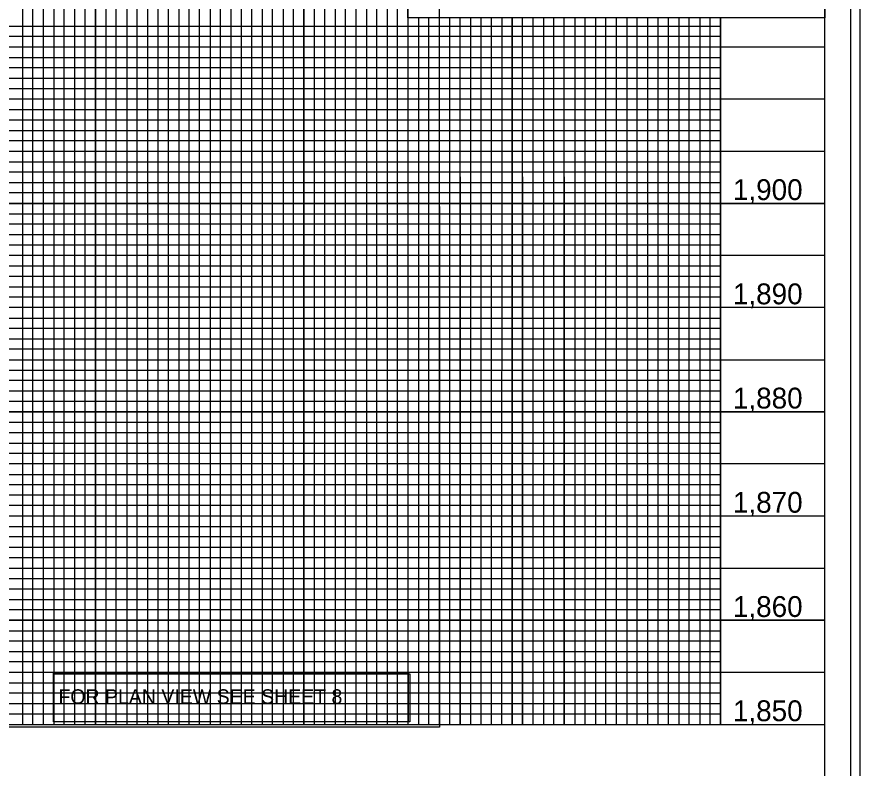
# Model space of a CAD drawing. Extents: x 557032 to 558716, y 525869 to 526969.
# Drawn here: x 558311.7 to 558716.5, y 526423.3 to 526783.7 of the extents above; entities that cross this region are included whole.
import ezdxf

# ---------------------------------------------------------------- set-up
doc = ezdxf.new("R2010")
doc.units = 0
for name, color, linetype in [('Exist Vertical Profile Vertical Axis Label', 7, 'Continuous'), ('Prop VPI Label', 7, 'Continuous'), ('Scratch_Level_5', 7, 'Continuous'), ('Sheet DOT Grid CELL', 7, 'Continuous'), ('Sheet Layout Profile Border Port 1', 7, 'Continuous'), ('Sheet Plot Border Inside CELL', 7, 'Continuous'), ('Sheet Plot Border Outside CELL', 7, 'Continuous'), ('Sheet Profile CELL', 7, 'Continuous'), ('Sheet Profile Grid Major CELL', 7, 'Continuous'), ('Sheet Profile Grid Middle CELL', 7, 'Continuous'), ('Sheet Profile Grid Minor CELL', 7, 'Continuous'), ('Sheet Sticker Exception Certification CELL', 7, 'Continuous')]:
    doc.layers.add(name, color=color, linetype=linetype)

msp = doc.modelspace()

# ---------------------------------------------------------------- linework, layer by layer
at = {"layer": 'Prop VPI Label'}
for points in [[(558329.22, 526469.22), (558499.45, 526469.22), (558499.45, 526445.55), (558329.22, 526445.55)], [(558329.22, 526468.46), (558500.36, 526468.46), (558500.36, 526445.55), (558329.22, 526445.55)]]:
    msp.add_lwpolyline(points, close=True, dxfattribs=at)
at = {"layer": 'Scratch_Level_5'}
msp.add_lwpolyline([(557999.45, 526942.96), (558514.45, 526942.96), (558514.5, 526442.96), (557999.5, 526442.96)], close=True, dxfattribs=at)
at = {"layer": 'Sheet DOT Grid CELL'}
for p, q in [((558349.45, 526444.22), (558349.45, 526944.22)), ((558399.45, 526444.22), (558399.45, 526944.22)), ((558449.45, 526444.22), (558449.45, 526944.22)), ((558499.45, 526444.22), (558499.45, 526806.67)), ((558549.45, 526444.22), (558549.45, 526783.17)), ((558599.45, 526444.22), (558599.45, 526783.17)), ((558649.45, 526444.22), (558649.45, 526783.17)), ((558699.45, 526694.22), (557199.45, 526694.22)), ((558699.45, 526644.22), (557199.45, 526644.22)), ((558699.45, 526594.22), (557199.45, 526594.22)), ((558699.45, 526544.22), (557199.45, 526544.22)), ((558699.45, 526494.22), (557199.45, 526494.22))]:
    msp.add_line(p, q, dxfattribs=at)
at = {"layer": 'Sheet Layout Profile Border Port 1'}
msp.add_lwpolyline([(557249.45, 526783.17), (557249.45, 526444.22), (558649.45, 526444.22), (558649.45, 526783.17)], dxfattribs=at)
at = {"layer": 'Sheet Plot Border Inside CELL'}
msp.add_lwpolyline([(557045.45, 525891.67), (558711.95, 525891.67), (558711.95, 526946.77), (557045.45, 526946.77)], close=True, dxfattribs=at)
at = {"layer": 'Sheet Plot Border Outside CELL'}
msp.add_lwpolyline([(557032.45, 525869.22), (558716.45, 525869.22), (558716.45, 526969.22), (557032.45, 526969.22)], close=True, dxfattribs=at)
at = {"layer": 'Sheet Profile CELL'}
msp.add_line((557199.45, 526444.22), (558699.45, 526444.22), dxfattribs=at)
msp.add_lwpolyline([(558699.45, 526944.22), (557199.45, 526944.22), (557199.45, 525894.22), (558699.45, 525894.22)], close=True, dxfattribs=at)
at = {"layer": 'Sheet Profile Grid Major CELL'}
for points in [[(558299.45, 526944.22), (558349.45, 526944.22), (558349.45, 526444.22), (558399.45, 526444.22), (558399.45, 526944.22), (558449.45, 526944.22), (558449.45, 526444.22), (558499.45, 526444.22), (558499.45, 526944.22), (558525.75, 526944.22)], [(558649.45, 526783.17), (558649.45, 526444.22), (558699.45, 526444.22), (558699.45, 526794.22)], [(558549.45, 526783.17), (558549.45, 526444.22), (558599.45, 526444.22), (558599.45, 526444.22), (558599.45, 526783.17)], [(558699.45, 526744.22), (557199.45, 526744.22), (557199.45, 526694.22), (558699.45, 526694.22)], [(558699.45, 526644.22), (557199.45, 526644.22), (557199.45, 526594.22), (558699.45, 526594.22)], [(558699.45, 526544.22), (557199.45, 526544.22), (557199.45, 526544.22), (557199.45, 526494.22), (558699.45, 526494.22)]]:
    msp.add_lwpolyline(points, dxfattribs=at)
at = {"layer": 'Sheet Profile Grid Middle CELL'}
for points in [[(558274.45, 526444.22), (558324.45, 526444.22), (558324.45, 526944.22), (558374.45, 526944.22), (558374.45, 526444.22), (558424.45, 526444.22), (558424.45, 526944.22), (558474.45, 526944.22), (558474.45, 526444.22), (558524.45, 526444.22), (558524.45, 526783.17)], [(558524.45, 526707.02), (558524.45, 526444.22), (558574.45, 526444.22), (558574.45, 526783.17)], [(558574.45, 526707.02), (558574.45, 526444.22), (558624.45, 526444.22), (558624.45, 526783.17)], [(558699.45, 526769.22), (557199.45, 526769.22), (557199.45, 526719.22), (558524.45, 526719.22)], [(558524.45, 526719.22), (558699.45, 526719.22)], [(558699.45, 526669.22), (557199.45, 526669.22), (557199.45, 526619.22), (558699.45, 526619.22)], [(558699.45, 526569.22), (557199.45, 526569.22), (557199.45, 526519.22), (558699.45, 526519.22)], [(558699.45, 526469.22), (557199.45, 526469.22)]]:
    msp.add_lwpolyline(points, dxfattribs=at)
at = {"layer": 'Sheet Profile Grid Minor CELL'}
for p, q in [((557249.45, 526779.22), (558649.45, 526779.22)), ((558649.45, 526759.22), (557249.45, 526759.22)), ((557249.45, 526754.22), (558649.45, 526754.22)), ((558649.45, 526734.22), (557249.45, 526734.22)), ((557249.45, 526729.22), (558649.45, 526729.22)), ((558649.45, 526709.22), (557249.45, 526709.22)), ((557249.45, 526704.22), (558649.45, 526704.22)), ((558649.45, 526699.22), (557249.45, 526699.22)), ((557249.45, 526689.22), (558649.45, 526689.22)), ((558649.45, 526684.22), (557249.45, 526684.22)), ((557249.45, 526679.22), (558649.45, 526679.22)), ((558649.45, 526674.22), (557249.45, 526674.22)), ((557249.45, 526664.22), (558649.45, 526664.22)), ((558649.45, 526659.22), (557249.45, 526659.22)), ((557249.45, 526654.22), (558649.45, 526654.22)), ((558649.45, 526649.22), (557249.45, 526649.22)), ((557249.45, 526639.22), (558649.45, 526639.22)), ((558649.45, 526634.22), (557249.45, 526634.22)), ((557249.45, 526629.22), (558649.45, 526629.22)), ((558649.45, 526624.22), (557249.45, 526624.22)), ((557249.45, 526614.22), (558649.45, 526614.22)), ((558649.45, 526609.22), (557249.45, 526609.22)), ((557249.45, 526604.22), (558649.45, 526604.22)), ((558649.45, 526599.22), (557249.45, 526599.22)), ((557249.45, 526589.22), (558649.45, 526589.22)), ((558649.45, 526584.22), (557249.45, 526584.22)), ((557249.45, 526579.22), (558649.45, 526579.22)), ((558649.45, 526574.22), (557249.45, 526574.22)), ((557249.45, 526564.22), (558649.45, 526564.22)), ((558649.45, 526559.22), (557249.45, 526559.22)), ((558649.45, 526554.22), (557249.45, 526554.22)), ((558649.45, 526549.22), (557249.45, 526549.22)), ((557249.45, 526539.22), (558649.45, 526539.22)), ((558649.45, 526534.22), (557249.45, 526534.22)), ((557249.45, 526529.22), (558649.45, 526529.22)), ((558649.45, 526524.22), (557249.45, 526524.22)), ((557249.45, 526514.22), (558649.45, 526514.22)), ((558649.45, 526509.22), (557249.45, 526509.22)), ((557249.45, 526504.22), (558649.45, 526504.22)), ((558649.45, 526499.22), (557249.45, 526499.22)), ((557249.45, 526489.22), (558649.45, 526489.22)), ((558649.45, 526484.22), (557249.45, 526484.22)), ((557249.45, 526479.22), (558649.45, 526479.22)), ((558649.45, 526474.22), (557249.45, 526474.22)), ((557249.45, 526464.22), (558649.45, 526464.22)), ((558649.45, 526459.22), (557249.45, 526459.22)), ((557249.45, 526454.22), (558649.45, 526454.22))]:
    msp.add_line(p, q, dxfattribs=at)
for points in [[(558314.45, 526944.22), (558314.45, 526444.22), (558319.45, 526444.22), (558319.45, 526944.22)], [(558329.45, 526944.22), (558329.45, 526444.22), (558334.45, 526444.22), (558334.45, 526944.22)], [(558339.45, 526944.22), (558339.45, 526444.22), (558344.45, 526444.22), (558344.45, 526944.22)], [(558354.45, 526944.22), (558354.45, 526444.22), (558359.45, 526444.22), (558359.45, 526944.22)], [(558364.45, 526944.22), (558364.45, 526444.22), (558369.45, 526444.22), (558369.45, 526944.22)], [(558379.45, 526944.22), (558379.45, 526444.22), (558384.45, 526444.22), (558384.45, 526944.22)], [(558389.45, 526944.22), (558389.45, 526444.22)], [(558389.45, 526444.22), (558394.45, 526444.22), (558394.45, 526944.22)], [(558404.45, 526944.22), (558404.45, 526444.22), (558409.45, 526444.22), (558409.45, 526944.22)], [(558414.45, 526944.22), (558414.45, 526444.22), (558419.45, 526444.22), (558419.45, 526944.22)], [(558429.45, 526944.22), (558429.45, 526444.22), (558434.45, 526444.22), (558434.45, 526944.22)], [(558439.45, 526944.22), (558439.45, 526444.22), (558444.45, 526444.22), (558444.45, 526944.22)], [(558454.45, 526944.22), (558454.45, 526444.22), (558459.45, 526444.22), (558459.45, 526944.22)], [(558464.45, 526944.22), (558464.45, 526444.22), (558469.45, 526444.22), (558469.45, 526944.22)], [(558479.45, 526944.22), (558479.45, 526444.22), (558484.45, 526444.22), (558484.45, 526944.22)], [(558489.45, 526944.22), (558489.45, 526444.22), (558494.45, 526444.22), (558494.45, 526944.22)], [(558504.45, 526783.17), (558504.45, 526444.22), (558509.45, 526444.22), (558509.45, 526783.17)], [(558514.45, 526783.17), (558514.45, 526444.22), (558519.45, 526444.22), (558519.45, 526783.17)], [(558529.45, 526783.17), (558529.45, 526444.22), (558529.45, 526444.22), (558534.45, 526444.22), (558539.45, 526444.22), (558539.45, 526783.17)], [(558534.45, 526783.17), (558534.45, 526444.22)], [(558544.45, 526783.17), (558544.35, 526444.27), (558549.35, 526444.27), (558554.45, 526444.22), (558554.45, 526783.17)], [(558554.45, 526707.02), (558554.45, 526444.22), (558559.45, 526444.22), (558559.45, 526783.17)], [(558564.45, 526783.17), (558564.45, 526444.22), (558569.45, 526444.22), (558569.45, 526783.17)], [(558579.45, 526783.17), (558579.45, 526444.22), (558584.45, 526444.22), (558584.45, 526783.17)], [(558589.45, 526783.17), (558589.45, 526444.22), (558594.45, 526444.22), (558594.45, 526783.17)], [(558604.45, 526783.17), (558604.45, 526444.22), (558609.45, 526444.22), (558609.45, 526783.17)], [(558614.45, 526783.17), (558614.45, 526444.22), (558619.45, 526444.22), (558619.45, 526783.17)], [(558629.45, 526783.17), (558629.45, 526444.22), (558634.45, 526444.22), (558634.45, 526783.17)], [(558639.45, 526783.17), (558639.45, 526444.22), (558644.45, 526444.22), (558644.45, 526783.17)], [(558649.45, 526774.22), (557249.45, 526774.22), (557249.45, 526764.22), (558649.45, 526764.22)], [(558649.45, 526749.22), (557249.45, 526749.22), (557249.45, 526739.22), (558649.45, 526739.22)], [(558649.45, 526724.22), (557249.45, 526724.22), (557249.45, 526714.22), (558649.45, 526714.22)], [(558649.45, 526449.22), (557249.45, 526449.22)]]:
    msp.add_lwpolyline(points, dxfattribs=at)
at = {"layer": 'Sheet Sticker Exception Certification CELL'}
for p, q in [((558499.4, 526783.17), (558499.4, 526806.67)), ((558499.4, 526783.17), (558499.4, 526806.67)), ((558699.44, 526806.66), (558699.44, 526783.16)), ((558699.44, 526806.66), (558699.44, 526783.16)), ((558699.44, 526783.17), (558499.4, 526783.17)), ((558699.44, 526783.17), (558499.4, 526783.17))]:
    msp.add_line(p, q, dxfattribs=at)

# ---------------------------------------------------------------- texts
at = {"layer": 'Exist Vertical Profile Vertical Axis Label'}
for s, p in [('1,900', (558655.39, 526695.81)), ('1,890', (558655.39, 526645.81)), ('1,880', (558655.39, 526595.81)), ('1,870', (558655.39, 526545.81)), ('1,860', (558655.39, 526495.81)), ('1,850', (558655.39, 526445.81))]:
    msp.add_text(s, height=10, dxfattribs=at).set_placement(p)
at = {"layer": 'Prop VPI Label'}
msp.add_text('FOR PLAN VIEW SEE SHEET 8', height=7, dxfattribs=at).set_placement((558331.66, 526454.11))

doc.saveas('drawing.dxf')
